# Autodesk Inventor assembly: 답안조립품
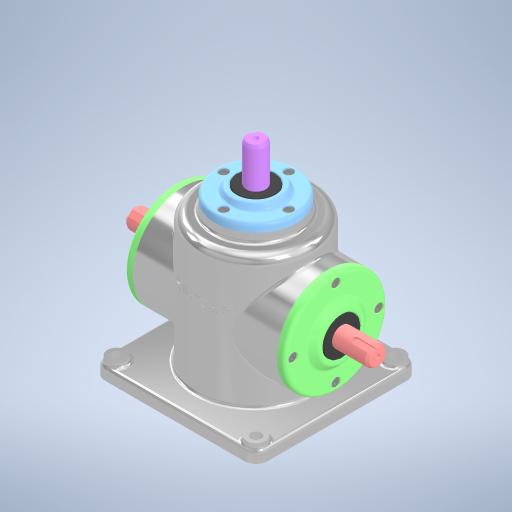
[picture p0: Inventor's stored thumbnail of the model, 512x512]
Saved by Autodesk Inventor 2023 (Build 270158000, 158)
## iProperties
Created: 2025-05
Part Number: 답안조립품
Document SubType Name: Assembly
Designer: ADMIN_PC
Author: ADMIN_PC
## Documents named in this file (13)
- C:\Users\ADMIN_PC\Desktop\750505V1006\답안조립품.iam
- C:\Users\ADMIN_PC\Desktop\750505V1006\본체.ipt
- C:\Users\ADMIN_PC\Desktop\750505V1006\측면 커버.ipt
- C:\Users\ADMIN_PC\Desktop\750505V1006\깊은 홈 볼 베어링 6203.ipt
- C:\Users\ADMIN_PC\Desktop\750505V1006\오일 실 17 32 8.ipt
- C:\Users\ADMIN_PC\Desktop\750505V1006\윗 커버.ipt
- C:\Users\ADMIN_PC\Desktop\750505V1006\메인 축.ipt
- C:\Users\ADMIN_PC\Desktop\750505V1006\평행 키 5x5.ipt
- C:\Users\ADMIN_PC\Desktop\750505V1006\메인 베벨기어.ipt
- C:\Users\ADMIN_PC\Desktop\750505V1006\6각 구멍붙이 볼트 M4-10L.ipt
- C:\Users\ADMIN_PC\Desktop\750505V1006\서브 축.ipt
- C:\Users\ADMIN_PC\Desktop\750505V1006\평행 키 4x4.ipt
- C:\Users\ADMIN_PC\Desktop\750505V1006\서브 베벨기어.ipt
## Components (12 placed, 1 different names)
1. 6각 구멍붙이 볼트 M4-10L:1
2. 6각 구멍붙이 볼트 M4-10L:2
3. 6각 구멍붙이 볼트 M4-10L:3
4. 6각 구멍붙이 볼트 M4-10L:4
5. 6각 구멍붙이 볼트 M4-10L:5
6. 6각 구멍붙이 볼트 M4-10L:6
7. 6각 구멍붙이 볼트 M4-10L:7
8. 6각 구멍붙이 볼트 M4-10L:8
9. 6각 구멍붙이 볼트 M4-10L:9
10. 6각 구멍붙이 볼트 M4-10L:10
11. 6각 구멍붙이 볼트 M4-10L:11
12. 6각 구멍붙이 볼트 M4-10L:12
